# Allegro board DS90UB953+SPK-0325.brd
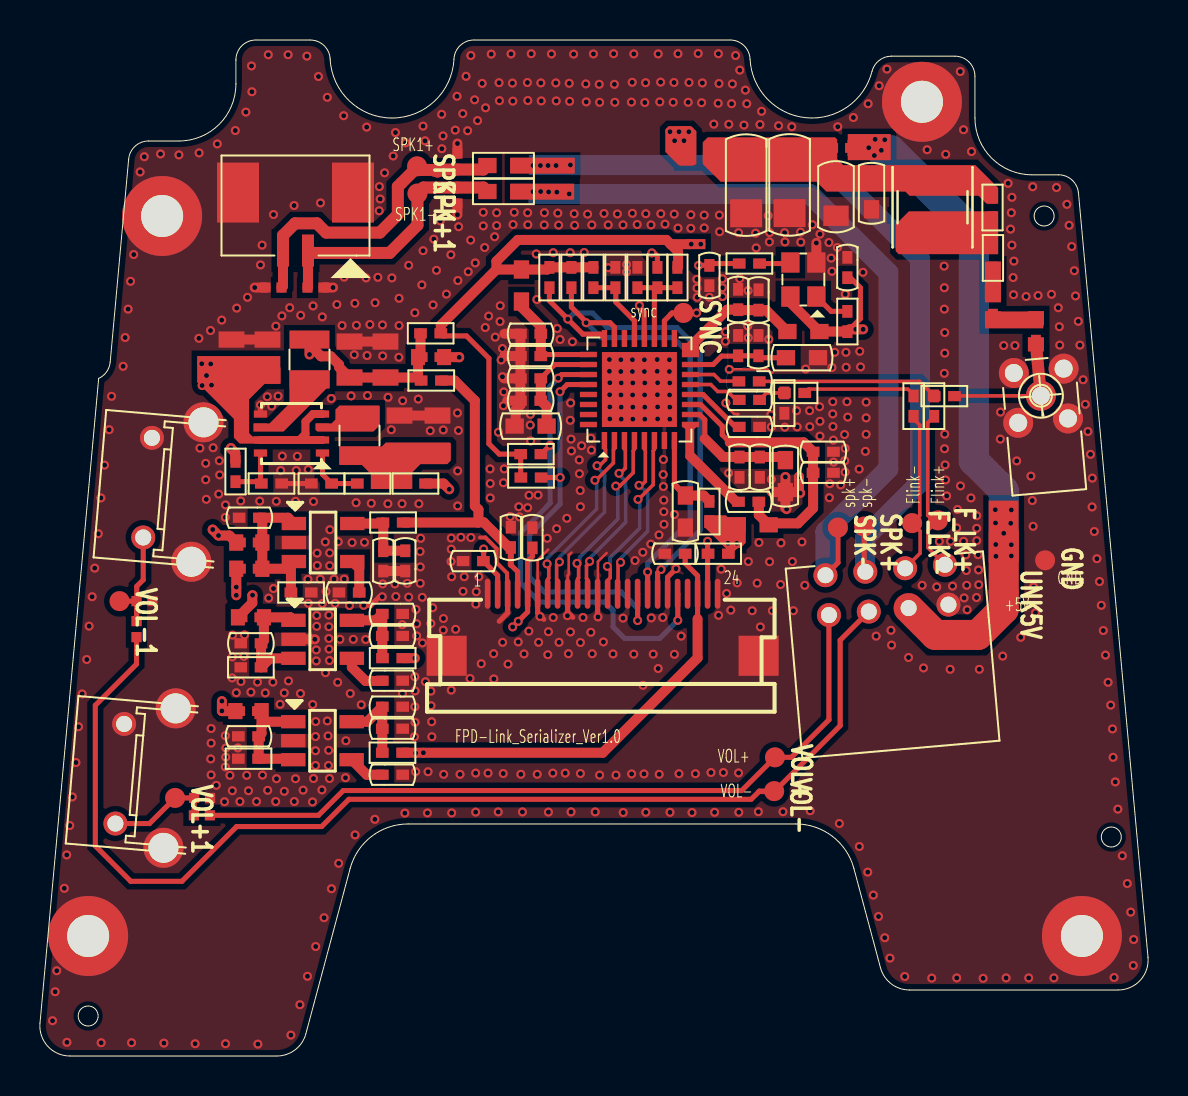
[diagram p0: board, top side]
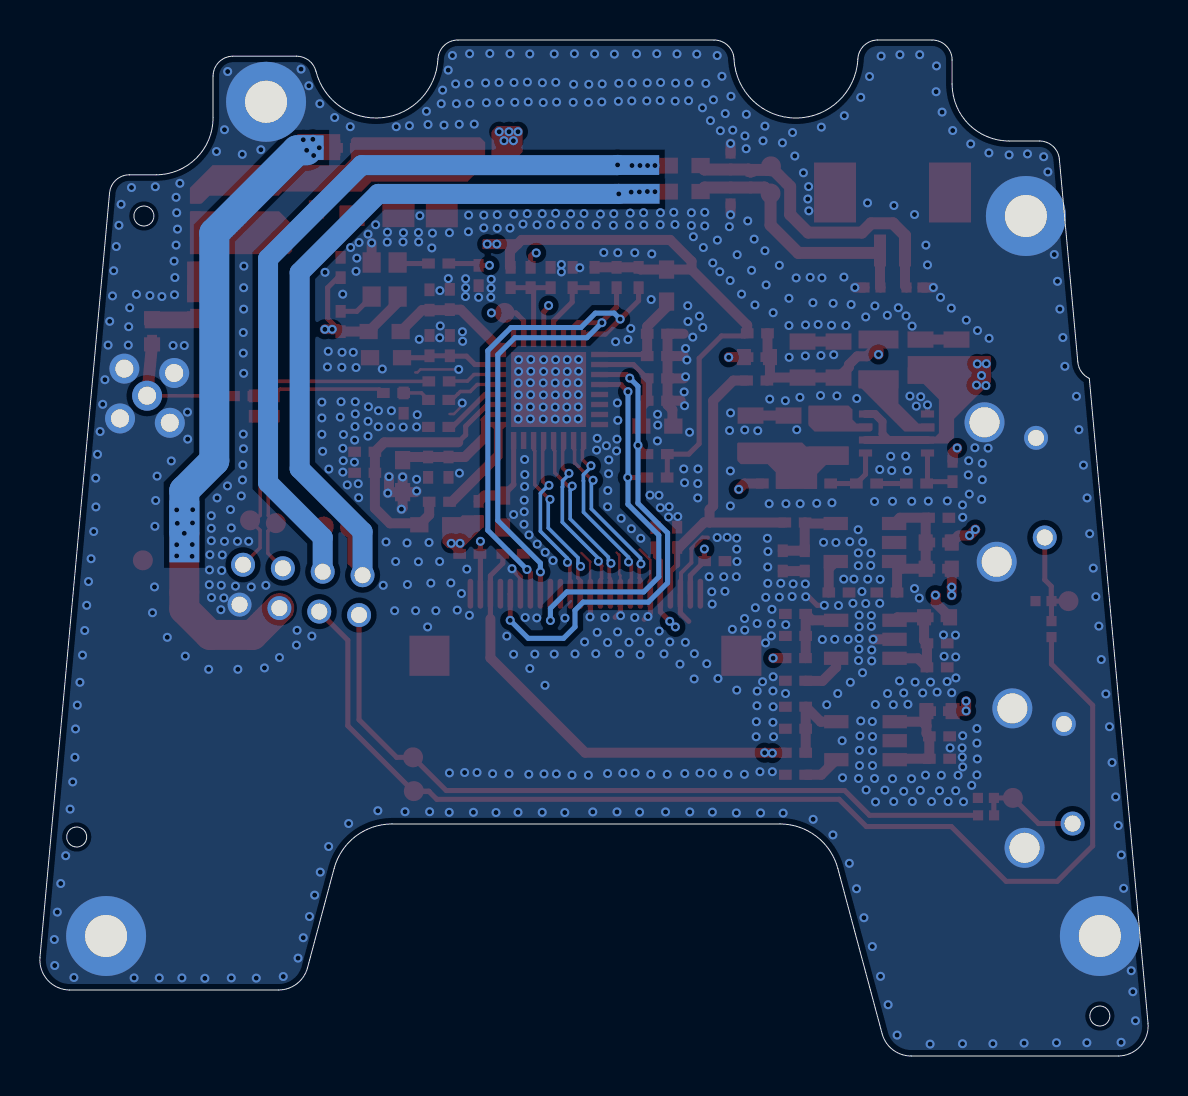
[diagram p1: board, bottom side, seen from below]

Outline 55.41 x 50.8 mm; copper layers: TOP, GND, POWER, BOTTOM. Coordinates in mm from the lower left corner of the outline.
Outline path: circle c2.41,2 r0.5 ; circle c50.22,42 r0.5 ; circle c53.58,10.95 r0.5 ; 1.49,0 arc(0.39,0.49) 0,1.64 2.93,33.88 arc(3.33,34.21) 3.51,34.7 4.43,44.84 arc(4.76,45.49) 5.43,45.75 6.95,45.75 arc(8.96,46.58) 9.8,48.6 9.8,49.8 arc(10.09,50.51) 10.8,50.8 13.51,50.8 arc(14.2,50.52) 14.51,49.85 arc(17.61,46.9) 20.7,49.85 arc(21.01,50.52) 21.7,50.8 34.51,50.8 arc(35.2,50.52) 35.51,49.85 arc(38.3,46.92) 41.61,49.24 arc(41.97,49.78) 42.58,49.99 45.76,49.99 arc(46.47,49.7) 46.76,48.99 46.76,46.91 arc(47.59,44.89) 49.61,44.06 50.94,44.06 arc(51.61,43.8) 51.94,43.15 55.41,4.94 arc(55.03,3.79) 53.92,3.3 43.48,3.3 arc(42.57,3.61) 42.03,4.41 40.7,9.38 arc(39.63,10.98) 37.81,11.6 18.41,11.6 arc(16.58,10.98) 15.51,9.38 13.3,1.11 arc(12.76,0.31) 11.85,0 1.49,0

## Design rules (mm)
net group N133411: nets N133411 N133415

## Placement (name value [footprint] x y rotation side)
C1  10uF  [C0603]  24.54 31.49 180 top
C2  0.1uF  [C0402]  24.54 32.76 180 top
C3  0.01uF  [C0402]  24.54 33.88 180 top
C4  10uF  [C0603]  38.11 34.91 0 top
C5  0.1uF  [C0402]  35.93 35.52 90 top
C6  0.01uF  [C0402]  34.92 35.52 90 top
C7  10uF  [C0603]  37.28 28.99 270 top
C8  0.1uF  [C0402]  36 29.44 270 top
C9  0.01uF  [C0402]  34.99 29.44 270 top
C10  0.033uF  [C0402]  35.46 33.73 0 top
C12  1uF  [C0402]  24.54 35 180 top
C13  0.01uF  [C0402]  24.54 36.11 180 top
C14  1uF  [C0402]  34.92 37.82 90 top
C15  0.01uF  [C0402]  35.93 37.8 90 top
C16  1uF  [C0402]  39.17 30.21 0 top
C17  0.01uF  [C0402]  39.17 29.16 0 top
C18  0.022uF  [C0402]  35.44 27.71 180 top
C19  0.1uF  [C0402]  35.48 31.45 0 top
C20  10uF  [C0603]  32.28 27.22 270 top
C21  NP  [C0402]  21.67 24.74 0 top
C22  @4.7uF/25V  [C0805]  39.81 42.96 270 top
C23  @0.1uF/25V  [C0603]  41.59 43.13 270 top
C36  0.01uF  [C0402]  40.38 39.42 90 top
C6893  1UF  [C0402]  10.43 15.98 0 top
C6894  1UF  [C0402]  17.63 16.36 180 top
C6895  100nF  [C0402]  17.63 14.06 180 top
C6999  2.2UF  [C0402]  17.63 17.46 0 top
C7011  1UF  [C0402]  10.47 26.91 0 top
C7012  1UF  [C0402]  17.17 24.75 90 top
C7013  100nF  [C0402]  15.46 23.17 0 top
C7014  2.2UF  [C0402]  18.27 24.75 270 top
C7019  NC  [C1206]  37.49 43.55 270 top
C7020  NC  [C1206]  35.32 43.54 270 top
C7321  @100PF  [2P0402R]  20.88 44.72 270 top
C7322  @100PF  [2P0402R]  20.88 43.02 90 top
C7346  22UF/10V  [2P0805R]  9.58 34.92 270 top
C7347  22UF/10V  [2P0805R]  11.38 34.92 270 top
C7348  22UF  [2P0805R]  19.88 31.12 270 top
C7349  22UF  [2P0805R]  17.98 31.12 270 top
C7350  22UF  [2P0805R]  15.48 34.82 270 top
C7351  22UF  [2P0805R]  17.28 34.82 270 top
C7352  0.033uF  [C0402]  35.48 32.8 0 top
C7501  @100nF/25V_2  [2P0402R]  19.88 43.82 90 top
C7502  NC  [C0402]  33.48 39.02 90 top
C7503  1UF  [C0402]  10.55 20.63 0 top
C7504  1UF  [C0402]  17.63 21 180 top
C7505  100nF  [C0402]  17.63 18.76 180 top
C7506  2.2UF  [C0402]  17.63 22.1 0 top
C7508  0.1uF  [C0402]  23.55 25.93 90 top
C7509  0.1uF  [C0402]  24.63 25.91 90 top
C7510  0.1uF  [C0402]  31.76 25.11 180 top
F_LK+  DNI(TP1_3)  [TP32]  44.91 26.78 0 top
F_LK-  DNI(TP1_3)  [TP32]  43.62 26.64 0 top
GND  DNI(TP1_3)  [TP32]  50.27 24.78 0 top
H1  HOLE1  [HOLE4P0CIR2P1]  2.41 6 0 top
H2  HOLE1  [HOLE4P0CIR2P1]  52.11 6 0 top
H3  HOLE1  [HOLE4P0CIR2P1]  44.11 47.71 0 top
H4  HOLE1  [HOLE4P0CIR2P1]  6.11 42 0 top
J1  CON26  [FPC0520D-M24-00RW]  21.39 23.11 180 top
J2  @JC3.660.047  [MMCXKWE]  50.06 33.01 275 top
J3  -  [FWF20006-D08B22W5B]  42.36 23.3 275 top
J2527  -  [Y2-8090V]  4.21 16.6 265 top
J2528  -  [Y2-8090V]  5.6 30.91 265 top
J2529  A1500WV-S-02P  [4PIN-CON-WF12502-01200]  12.78 42.32 180 top
L1  @MPZ1005F470ETD  [2P0402R_0603]  49.81 36.23 90 top
L2  @MPZ1005S331ETD  [2P0402R_0603]  47.66 37.53 90 top
L3  @10uH LQH3NPN100NG0  [SL2520_30X30_40X40]  44.64 42.43 270 top
L4  BLM18AG102SN1  [L0603H0_95]  24.08 38.52 90 top
L5  BLM18AG102SN1  [L0603H0_95]  38.18 36.22 0 top
L6  BLM18AG102SN1  [L0603H0_95]  35.64 26.56 180 top
L1003  1.5UH/0.65A  [2520_2016]  15.98 31.02 270 top
L1004  1.5UH/0.65A  [2520_2016]  13.48 34.82 90 top
R1  0R  [R0402]  30.88 38.92 90 top
R2  2K  [R0402]  26.58 38.92 270 top
R3  2K  [R0402]  25.48 38.92 270 top
R4  @49.9R/NC  [R0402]  37.23 32.64 270 top
R5  10K  [R0402]  27.68 38.92 270 top
R6  402R 1%  [R0402]  28.78 38.92 270 top
R7  10K  [R0402]  33.48 27.22 90 top
R8  @0R  [R0402]  47.66 39.9 90 top
R9  @4.02K_1%  [R0402]  47.64 42.42 90 top
R19  10K  [R0402]  40.38 36.72 90 top
R20  NC  [R0402]  35.48 39.62 180 top
R2567  806K/5%  [R0402]  16.38 28.62 0 top
R2568  825K/5%  [R0402]  14.08 28.62 0 top
R7209  1K  [2P0402R]  8.1 12.03 180 top
R7281  100K/5%  [R0402]  10.43 14.86 180 top
R7282  100K/5%  [R0402]  13.06 23.17 0 top
R7286  NC  [2P0402R_0603]  32.98 44.93 180 top
R7288  1K  [2P0402R]  4.83 21.34 90 top
R7291  0R  [R0603]  23.18 44.52 180 top
R7292  0R  [R0603]  23.18 43.22 180 top
R7293  0R  [2P0402R_0603]  40.09 45.4 180 top
R7297  806K/5%  [R0402]  9.78 29.22 90 top
R7298  412K/5%  [R0402]  11.58 28.62 180 top
R7302  NC  [R0402]  45.23 32.99 180 top
R7303  0R  [R0402]  17.63 15.16 0 top
R7304  0R  [R0402]  17.66 26.67 0 top
R7305  0R  [R0402]  18.78 28.62 0 top
R7306  0R  [R0402]  19.54 36.13 180 top
R7307  0R  [R0402]  37.74 33.15 0 top
R7308  NC  [R0402]  31.88 38.92 90 top
R7309  40.2K  [R0402]  29.88 38.92 270 top
R7310  NC  [R0402]  19.57 33.77 180 top
R7311  0R  [2P0402R_0603]  10.43 17.24 180 top
R7312  0R  [2P0402R_0603]  10.47 25.67 180 top
R7313  NC  [2P0402R_0603]  10.47 24.36 180 top
R7314  100K/5%  [R0402]  10.55 19.43 180 top
R7316  NC  [2P0402R_0603]  10.55 21.93 180 top
R7317  NC  [R0402]  17.64 19.89 0 top
R7318  NC  [2P0402R_0603]  19.56 34.94 0 top
R7319  @0R  [R0402]  44.72 32.49 90 top
R7320  @0R  [R0402]  43.69 32.49 90 top
R7321  10K  [R0402]  24.56 28.92 0 top
R7322  10K  [R0402]  24.55 30.09 0 top
R7323  10K  [R0402]  33.92 25.11 180 top
SPK+  DNI(TP1_3)  [TP32]  41.22 26.47 0 top
SPK+1  DNI(TP1_3)  [TP32]  18.88 43.12 0 top
SPK-  DNI(TP1_3)  [TP32]  39.91 26.42 0 top
SPK-1  DNI(TP1_3)  [TP32]  18.86 44.48 0 top
SYNC  DNI(TP1_3)  [TP32]  32.18 37.15 0 top
T31  LESD9D5.0CT5G  [2P0402R]  8.11 12.9 0 top
T32  LESD9D5.0CT5G  [2P0402R]  5.23 22.74 0 top
T33  LESD9D5.0CT5G  [2P0402R]  11.68 38.42 180 top
T34  LESD9D5.0CT5G  [2P0402R]  13.78 38.42 0 top
U1  DS90UB953TRHBTQ1  [QFN32-0_5-SQ5H0_85]  29.98 33.32 90 top
U2105  SGM2019-3.3YN5G/TR  [SOT23-5H1_0]  14.13 15.76 270 top
U2106  SGM2019-1.8YN5G/TR  [SOT23-5H1_0]  14.16 25.67 270 top
U2109  MP2122GJ  [TSOP8-0_65-SQ3_0H1_0]  12.58 31.12 90 top
U2110  SGM2019-1.2YN5G/TR  [SOT23-5H1_0]  14.14 20.83 270 top
UNK5V  DNI(TP1_3)  [TP32]  48.23 23.65 0 top
VOL+  DNI(TP1_3)  [TP32]  36.76 14.93 0 top
VOL+1  DNI(TP1_3)  [TP32]  6.76 12.9 0 top
VOL-  DNI(TP1_3)  [TP32]  36.72 13.24 0 top
VOL-1  DNI(TP1_3)  [TP32]  3.98 22.74 0 top
Y1  ASDMB-50.000MHZ  [CRY4-2520]  38.18 38.82 90 top

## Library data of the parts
C1-C10 C12-C23 C36 C7019 C7020 C7352 C7502 C7508-C7510 = CAP NP
C6893 C6894 C7011 C7012 C7503 C7504 = CAP NP_1
C6895 C7013 C7505 = CAP NP_0
C6999 C7014 C7506 = 0402C-47p_1
C7321 C7322 C7501 = CAP NP: Tolerance: #TOL; User Part Number: HAMP; signal model: DEFAULT_CAPACITOR_0.001pF_1_2
C7346-C7351 = CAP NP: Tolerance: #TOL; User Part Number: HAMP
F_LK+ F_LK- GND SPK+ SPK+1 SPK- SPK-1 SYNC UNK5V VOL+ VOL+1 VOL- VOL-1 = TP
H1-H4 = HEADER 1_0
J1 = CON26: User Part Number: HAMP; Tolerance: #TOL
J2 = BNC_0
J3 = CONN_6_M4_SIMCARD_7
J2527 J2528 = TS-022_1
J2529 = TS-022_0
L1 L2 = INDUCTOR_0: User Part Number: HAMP; Tolerance: #TOL
L3 = INDUCTOR IRON: User Part Number: HAMP; Tolerance: #TOL
L4-L6 = INDUCTOR_0
L1003 L1004 = INDUCTOR
R1-R9 R19 R20 R7291 R7292 R7302-R7310 R7317 R7319-R7323 = R
R2567 R2568 R7281 R7282 R7297 R7298 R7314 = R_6
R7209 R7288 = R_6: Tolerance: #TOL; User Part Number: HAMP
R7286 R7293 R7311-R7313 R7316 R7318 = R: User Part Number: HAMP; Tolerance: #TOL
T31-T34 = GCDIODE_ESD: Tolerance: #TOL; User Part Number: HAMP
U1 = ds90ub953-q1
U2105 U2106 U2110 = TPS22902_1
U2109 = SW_SPST_1
Y1 = ASDMB-50.000MHZ

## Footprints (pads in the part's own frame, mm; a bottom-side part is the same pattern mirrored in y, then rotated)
2P0402R
  rect 0.508x0.508 smd: 1(-0.4,0) 2(0.4,0)
2P0402R_0603
  rect 0.7x0.8 smd: 1(-0.65,0) 2(0.65,0)
2P0805R
  rect 0.813x1.295 smd: 1(-0.9,0) 2(0.9,0)
4PIN-CON-WF12502-01200
  rect 0.6x1.6 smd: 1(-0.625,2.05) 2(0.625,2.05)
  rect 2.1x3 smd: 3(-2.875,-0.85) 4(2.875,-0.85)
2520_2016
  rect 0.9x2 smd: 1(-1,0) 2(1,0)
C0402
  rect 0.635x0.508 smd: 1(-0.508,0) 2(0.508,0)
C0603
  rect 0.914x0.762 smd: 1(-0.8,0) 2(0.8,0)
C0805
  rect 1.016x1.27 smd: 1(-0.953,0) 2(0.953,0)
C1206
  rect 1.397x1.6 smd: 1(-1.41,0) 2(1.41,0)
CRY4-2520
  rect 1.016x0.914 smd: 1(-0.851,-0.65) 2(0.851,-0.65) 3(0.851,0.65) 4(-0.851,0.65)
FPC0520D-M24-00RW
  oval 0.279x1.499 smd: 1(-1,0) 2(-1.5,0) 3(-2,0) 4(-2.5,0) 5(-3,0) 6(-3.5,0) 7(-4,0) 8(-4.5,0) 9(-5,0) 10(-5.5,0) 11(-6,0) 12(-6.5,0) 13(-7,0) 14(-7.5,0) 15(-8,0) 16(-8.5,0) 17(-9,0) 18(-9.5,0) 19(-10,0) 20(-10.5,0) 21(-11,0) 22(-11.5,0) 23(-12,0) 24(-12.5,0)
  rect 2.007x2.007 smd: 25(1.05,3.1) 26(-14.55,3.1)
FWF20006-D08B22W5B
  round 1.2 hole 0.8: 1(-1,3) 2(-1,1) 3(-1,-1) 4(-1,-3) 5(1,-3) 6(1,-1) 7(1,1) 8(1,3)
HOLE4P0CIR2P1
  round 4 hole 2.1: 1(0,0)
L0603H0_95
  rect 0.914x0.762 smd: 1(-0.8,0) 2(0.8,0)
MMCXKWE
  round 1.5 hole 0.9: 1(0,0) 2(1.25,1.25) 3(1.25,-1.25) 4(-1.25,-1.25) 5(-1.25,1.25)
QFN32-0_5-SQ5H0_85
  rect 0.851x0.269 smd: 1(-2.55,1.75) 2(-2.55,1.25) 3(-2.55,0.749) 4(-2.55,0.249) 5(-2.55,-0.249) 6(-2.55,-0.749) 7(-2.55,-1.25) 8(-2.55,-1.75) 17(2.55,-1.75) 18(2.55,-1.25) 19(2.55,-0.749) 20(2.55,-0.249) 21(2.55,0.249) 22(2.55,0.749) 23(2.55,1.25) 24(2.55,1.75)
  rect 0.269x0.851 smd: 9(-1.75,-2.55) 10(-1.25,-2.55) 11(-0.749,-2.55) 12(-0.249,-2.55) 13(0.249,-2.55) 14(0.749,-2.55) 15(1.25,-2.55) 16(1.75,-2.55) 25(1.75,2.55) 26(1.25,2.55) 27(0.749,2.55) 28(0.249,2.55) 29(-0.249,2.55) 30(-0.749,2.55) 31(-1.25,2.55) 32(-1.75,2.55)
  rect 3.749x3.749 smd: 33(0,0)
R0402
  rect 0.635x0.508 smd: 1(-0.508,0) 2(0.508,0)
R0603
  rect 0.914x0.762 smd: 1(-0.8,0) 2(0.8,0)
SL2520_30X30_40X40
  rect 1.092x3.683 smd: 1(-1.501,0) 2(1.501,0)
SOT23-5H1_0
  rect 0.66x1.219 smd: 1(-0.95,-1.46) 2(0,-1.46) 3(0.95,-1.46) 4(0.95,1.46) 5(-0.95,1.46)
TP32
  round 1 smd: 1(0,0)
TSOP8-0_65-SQ3_0H1_0
  rect 0.356x0.66 smd: 1(-0.975,-1.55) 2(-0.325,-1.55) 3(0.325,-1.55) 4(0.975,-1.55) 5(0.975,1.55) 6(0.325,1.55) 7(-0.325,1.55) 8(-0.975,1.55)
Y2-8090V
  round 1.2 hole 0.8: 1(5,0) 2(0,0)
  round 2 hole 1.5: 3(6,2.5) 4(-1,2.5)

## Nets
GND: C1.2 C2.2 C3.2 C4.2 C5.2 C6.2 C7.2 C8.2 C9.2 C12.2 C13.2 C14.2 C15.2 C16.2 C17.2 C19.2 C20.2 C21.1 C22.2 C23.2 C36.2 C6893.1 C6894.1 C6895.1 C6999.2 C7011.1 C7012.1 C7013.1 C7014.2 C7019.2 C7020.2 C7321.1 C7322.1 C7346.1 C7347.1 C7348.1 C7349.1 C7350.1 C7351.1 C7502.1 C7503.1 C7504.1 C7505.1 C7506.2 C7508.2 C7509.2 C7510.2 GND.1(TP) H1.1 H2.1 H3.1 H4.1 J1.1 J1.3 J1.6 J1.9 J1.12 J1.15 J1.19 J1.24 J1.25 J1.26 J2.2 J2.3 J2.4 J2.5 J3.8(GND2) J2527.2(S2) J2527.3(GND1) J2527.4(GND2) J2528.2(S2) J2528.3(GND1) J2528.4(GND2) J2529.3(GND1) J2529.4(GND2) R4.2 R6.1 R2568.1 R7281.2 R7282.2 R7298.1 R7309.1 R7314.2 T31.2 T32.2 T33.2 T34.2 U1.7(RES0) U1.33(DAP) U2105.2(GND) U2106.2(GND) U2109.5(GND) U2110.2(GND) Y1.2(GND)
VDD_1V8: C36.1 L4.2 L5.2 L6.2 R2.1 R3.1 R5.1 R7.1 R19.1 R7306.1 R7308.2 R7321.1 R7322.1 R7323.1 Y1.4(VDD)
VDD_5V: C7346.2 C7347.2 R7286.2 R7311.2 R7312.2 U2109.2(EN2) U2109.4(EN1) U2109.7(IN)
VDD_LDO: R7316.2 R7318.2
CAM_1V2: C7509.1 J1.5 R7305.2 R7317.2
CAM_1V8: C7508.1 J1.4 R7304.2 R7310.1
CAM_3V3: C7510.1 J1.22 R7303.2 R7313.2
CAM_CLK: C21.2 J1.2 R1.2
CAM_CLKO: R1.1 R7308.1 R7309.2 U1.19(CLK_OUT/IDX)
CAM_PWD: J1.16 R7321.2 U1.28(GPIO3)
CAM_RST: J1.20 R7322.2 U1.27(GPIO2)
CAM_SCL: J1.18 R3.2 U1.24(I2C_SCL)
CAM_SDA: J1.17 R2.2 U1.23(I2C_SDA)
CAM_SYNC: J1.23 R7323.2 SYNC.1(TP) U1.18(GPIO1)
CLK_IN: C7502.2 R20.2 U1.20(CLKIN)
CSI_CKN: J1.13 U1.6(CSI_CLKN)
CSI_CKP: J1.14 U1.5(CSI_CLKP)
CSI_D0N: J1.10 U1.4(CSI_D0N)
CSI_D0P: J1.11 U1.3(CSI_D0P)
CSI_D1N: J1.7 U1.2(CSI_D1N)
CSI_D1P: J1.8 U1.1(CSI_D1P)
FDP-LINK+: C10.2 R7302.2 R7319.2
FDP-LINK-: R7307.2 R7320.2
POC_V: C22.1 C23.1 C7019.1 C7020.1 L3.1 R9.2 R7286.1 R7293.2
PWR_5V: J3.7(PWR_5V) R7293.1 UNK5V.1
SPK+: J3.4(SPK-) R7292.1 SPK-.1(TP)
SPK-: J3.3(SPK+) R7291.1 SPK+.1(TP)
VOL+: J3.5(VOLUME+) R7209.1 VOL+.1(TP)
VOL-: J3.6(VOLUME-) R7288.1 VOL-.1(TP)
N00294: C1.1 C2.1 C3.1 U1.26(VDDD_CAP)
N00623: C4.1 C5.1 C6.1 U1.15(VDDDRV_CAP)
N01072: C7.1 C8.1 C9.1 U1.10(VDDPLL_CAP)
N03572: C10.1 U1.14(DOUT+)
N03592: C7352.1 U1.13(DOUT-)
N03606: J2.1 L1.1 R7302.1
N03646: C7352.2 R4.1 R7307.1
N04688: C12.1 C13.1 L4.1 U1.25(VDDD)
N05216: C14.1 C15.1 L5.1 U1.16(VDDDRV)
N05348: C16.1 C17.1 C18.1 L6.1 U1.11(VDDDPLL)
N05546: C18.2 U1.9(LPF1)
N05630: C19.1 U1.12(LPF2)
N08569: R5.2 R6.2 U1.21(MODE)
N08620: C20.1 R7.2 U1.8(PDB)
N10872: L1.2 L2.1
N10876: L2.2 R8.1
N10907: L3.2 R8.2 R9.1
N20067: R19.2 Y1.1(STB)
N20534: R20.1 Y1.3(OUT)
N40133: C6893.2 R7281.1 R7311.1 U2105.1(VIN) U2105.3(EN)
N40219: C6895.2 U2105.4(BP/FB)
N40223: C6894.2 C6999.1 R7303.1 U2105.5(VOUT)
N40778: C7011.2 R7282.1 R7312.1 R7313.1 U2106.1(VIN) U2106.3(EN)
N40864: C7013.2 U2106.4(BP/FB)
N40868: C7012.2 C7014.1 R7304.1 U2106.5(VOUT)
N92182: J2527.1(S1) R7209.2 T31.1 VOL+1.1(TP)
N92991: J2528.1(S1) R7288.2 T32.1 VOL-1.1(TP)
N121438: L1003.1 U2109.3(SW2)
N121471: R2567.1 R2568.2 U2109.1(FB2)
N121478: C7348.2 C7349.2 L1003.2 R2567.2 R7305.1
N129833: R7297.1 R7298.2 U2109.8(FB1)
N129837: C7350.2 C7351.2 L1004.2 R7297.2 R7306.2 R7310.2 R7318.1
N131151: L1004.1 U2109.6(SW1)
N133411: C7322.2 C7501.1 J2529.1 R7292.2 SPK+1.1(TP) T34.1
N133415: C7321.2 C7501.2 J2529.2 R7291.2 SPK-1.1(TP) T33.1
N134026: F_LK+.1(TP) J3.1(FDP-LINK+) R7319.1
N134032: F_LK-.1(TP) J3.2(FDP-LINK-) R7320.1
N180611: C7503.2 R7314.1 R7316.1 U2110.1(VIN) U2110.3(EN)
N180695: C7504.2 C7506.1 R7317.1 U2110.5(VOUT)
N180699: C7505.2 U2110.4(BP/FB)

Pads without a net: J1 21; U1 17 22 29 30 31 32

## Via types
v1: diameter 0.45, hole 0.249, TOP to BOTTOM, 879 vias

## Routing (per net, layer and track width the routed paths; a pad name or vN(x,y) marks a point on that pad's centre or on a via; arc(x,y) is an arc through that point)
GND: length 47.3
  TOP w0.127: 36.64,34.18 36.53,34.18 36.38,34.33 v1(34.47,34.33) ; 25.42,25.32 24.89,24.79 J1.6 ; J1.12 27.9,23.13 27.9,24.72 28.34,25.15 ; 26.58,25.17 26.44,25.04 26.44,24.08 26.39,24.02 J1.9 ; v1(34.3,32.65) 34.33,32.62 34.33,32.48 34.71,32.1 34.93,32.1
  TOP w0.2: J1.3 23.36,23.14 23.36,24.15 22.84,24.67 22.84,25.36 22.28,25.92 22.01,25.92
  TOP w0.254: v1(17.12,22.96) 16.98,22.96 16.55,22.53 v1(16.19,22.53) ; 23.32,32.81 23.37,32.76 ; v1(31.81,24.36) 31.39,23.94 J1.19 ; J1.12 27.89,21.97 v1(27.91,21.95) ; v1(23.13,33.96) 23.21,33.88 ; 26.65,21.93 26.39,22.19 J1.9 ; R7298.1 R2568.1 ; U2109.5 v1(11.03,32.55) ; J1.6 24.89,22.14 25.2,21.83 ; 23.22,34.99 23.22,35 ; J1.3 23.39,22.15 22.97,21.73 ; 23.22,36.1 23.23,36.11
  TOP w0.327: v1(37.28,28.95) 37.28,28.98 ; 37.99,28.19 37.97,28.19
  TOP w0.5: C1.2 23.79,31.54 23.79,32.31 24.03,32.56 C2.2 ; 23.21,33.88 C3.2 ; C3.2 C12.2 ; C3.2 C2.2 ; C7321.1 v1(20.88,45.62) ; 23.37,32.76 C2.2 ; U2110.2 v1(13.75,20.83) ; C7349.1 C7348.1 ; C7.2 v1(37.28,28.95) ; C7.2 36.63,28.19 v1(36.58,28.24) ; C7.2 37.28,27.4 v1(37.34,27.34) ; C7.2 37.97,28.19 ; C12.2 23.22,35 ; C12.2 C13.2 23.23,36.11 ; 37.97,28.19 v1(38.02,28.14) ; 37.97,28.19 37.96,28.2 v1(37.96,28.96) ; C7014.2 C7012.1 ; C7350.1 C7351.1 ; C7322.1 v1(20.88,42.06) ; Y1.2 v1(38.83,40.65) ; T34.2 v1(14.66,38.42) ; C7347.1 C7346.1 ; T33.2 v1(10.74,38.42)
  GND w0.127: 28.33,28.83 28.21,28.43
  POWER w0.127: 9.19,23.46 9.39,23.66 9.39,23.73 9.45,23.8 9.72,24
  vias: v1(0.63,1.76) v1(0.84,4.26) v1(0.76,3.21) v1(1.22,8.38) v1(1.34,10.05) v1(1.35,0.68) v1(1.49,11.52) v1(1.62,12.95) v1(1.8,14.67) v1(1.93,16.46) v1(2.11,18.1) v1(2.34,19.82) v1(2.46,21.49) v1(2.61,22.96) v1(2.74,24.39) v1(2.92,26.11) v1(3.05,27.9) v1(3.06,0.66) v1(3.23,29.54) v1(3.46,31.31) v1(3.58,32.98) v1(4.16,34.48) v1(4.26,35.92) v1(4.41,37.34) v1(4.53,38.73) v1(4.58,0.66) v1(4.69,40.07) v1(5.01,44.2) v1(5.22,44.96) v1(6.03,45.1) v1(6.2,0.64) v1(6.95,45.05) v1(7.76,0.61) v1(7.96,45.15) v1(7.95,35.88) v1(8,30.39) v1(8.29,29.63) v1(8.29,28.81) v1(8.32,27.83) v1(8.53,36.27) v1(8.54,14.85) v1(8.56,16.37) v1(8.56,15.64) v1(8.56,14.05) v1(8.66,30.41) v1(8.82,13.53) v1(8.87,45.6) v1(8.94,28.09) v1(8.97,29.76) v1(8.99,29.05) v1(9.09,36.79) v1(9.23,12.71) v1(9.28,27.55) v1(9.27,26.93) v1(9.27,16.01) v1(9.3,15.4) v1(9.29,14.94) v1(9.27,14.45) v1(9.28,0.61) v1(9.5,14.03) v1(9.63,21.04) v1(9.62,19.95) v1(9.61,18.9) v1(9.62,13.26) v1(9.77,46.27) v1(9.84,37.39) v1(9.82,18.16) v1(9.9,15.4) v1(10.04,27.75) v1(10,12.72) v1(10.05,18.72) v1(10.23,21.05) v1(10.2,19.98) v1(10.3,47.19) v1(10.34,14.03) v1(10.38,37.93) v1(10.43,13.26) v1(10.58,49.5) v1(10.6,48.21) v1(10.55,18.19) v1(10.83,12.72) v1(10.88,18.69) v1(10.9,0.59) v1(11.03,39.55) v1(10.99,27.74) v1(11.11,40.54) v1(11.13,14.04) v1(11.27,18.15) v1(11.42,50.06) v1(11.37,32.96) v1(11.44,22.89) v1(11.39,13.28) v1(11.59,32.49) v1(11.68,42.07) v1(11.68,23.37) v1(11.65,18.69) v1(11.8,36.49) v1(11.82,27.73) v1(11.83,13.86) v1(11.79,12.72) v1(11.91,32.99) v1(12.04,29.27) v1(12.01,17.58) v1(12.1,37) v1(12.12,29.99) v1(12.22,18.15) v1(12.22,13.23) v1(12.41,50.06) v1(12.43,18.75) v1(12.49,37.41) v1(12.55,1.04) v1(12.71,42.52) v1(12.74,17.56) v1(12.72,12.72) v1(12.82,29.27) v1(12.78,27.73) v1(12.78,13.86) v1(12.87,29.98) v1(13.04,37.03) v1(13.03,18.12) v1(13,2.56) v1(13.16,13.29) v1(13.35,49.99) v1(13.42,29.32) v1(13.4,23.83) v1(13.42,22.63) v1(13.38,3.98) v1(13.64,17.57) v1(13.63,12.7) v1(13.66,37.5) v1(13.68,27.72) v1(13.68,13.87) v1(13.84,22.02) v1(13.84,21.48) v1(13.82,20.3) v1(13.82,19.75) v1(13.79,16.72) v1(13.78,15.97) v1(13.78,15.26) v1(13.78,14.52) v1(13.79,5.47) v1(13.93,48.97) v1(13.86,25.14) v1(13.87,24.52) v1(14.03,42.65) v1(14.02,23.84) v1(14.12,36.95) v1(14.12,22.62) v1(14.1,13.3) v1(14.21,6.91) v1(14.27,25.7) v1(14.31,23.22) v1(14.28,19.16) v1(14.37,47.93) v1(14.37,16.75) v1(14.41,16) v1(14.44,15.28) v1(14.43,14.52) v1(14.5,26.31) v1(14.49,25.15) v1(14.49,24.51) v1(14.45,22.04) v1(14.45,21.46) v1(14.45,20.87) v1(14.46,20.34) v1(14.48,19.77) v1(14.48,13.87) v1(14.57,32.87) v1(14.58,8.36) v1(14.71,23.84) v1(14.76,22.63) v1(14.85,37.57) v1(14.92,25.71) v1(14.89,18.68) v1(14.94,9.63) v1(15,20.83) v1(15.11,36.52) v1(15.19,47.01) v1(15.21,38.94) v1(15.22,23.84) v1(15.3,15.76) v1(15.28,13.91) v1(15.48,22.52) v1(15.52,18.12) v1(15.56,33) v1(15.61,25.67) v1(15.72,35.06) v1(15.67,20.83) v1(15.75,37.63) v1(15.83,36.53) v1(15.81,27.66) v1(15.76,11.05) v1(16.07,17.56) v1(16.23,25.68) v1(16.34,46.44) v1(16.31,38.9) v1(16.29,20.82) v1(16.36,35.02) v1(16.38,33.02) v1(16.5,36.57) v1(16.57,27.63) v1(16.76,37.66) v1(16.75,11.83) v1(16.9,38.93) v1(16.97,43.47) v1(17.01,42.85) v1(16.96,42.26) v1(17.13,36.55) v1(17.14,35) v1(17.14,23.6) v1(17.23,44.16) v1(17.41,32.93) v1(17.4,27.61) v1(17.6,38.9) v1(17.57,31.31) v1(17.66,45) v1(17.78,46.17) v1(17.75,23.6) v1(17.8,22.97) v1(17.96,37.88) v1(17.96,36.52) v1(17.95,34.93) v1(18.14,32.76) v1(18.11,27.61) v1(18.12,21.56) v1(18.13,18.12) v1(18.28,45.66) v1(18.25,12.14) v1(18.44,39.53) v1(18.37,23.63) v1(18.44,22.94) v1(18.73,15.96) v1(18.75,37.16) v1(18.81,22.33) v1(18.84,21.61) v1(18.84,21) v1(18.75,18.96) v1(18.76,18.25) v1(18.75,17.46) v1(18.76,16.68) v1(18.79,14.21) v1(18.92,32.84) v1(18.95,27.61) v1(19.04,25.88) v1(19.01,25.22) v1(19.02,24.45) v1(19.02,23.63) v1(19.1,38.55) v1(19.12,22.93) v1(19.13,20.65) v1(19.16,46.49) v1(19.16,40.26) v1(19.25,45.76) v1(19.28,18.71) v1(19.41,14.21) v1(19.38,12.15) v1(19.52,31.26) v1(19.64,22.41) v1(19.55,21.62) v1(19.55,18.24) v1(19.56,17.51) v1(19.59,16.71) v1(19.6,15.96) v1(19.7,40.84) v1(19.66,37.55) v1(19.83,39.28) v1(20.02,41.75) v1(20.09,47.08) v1(20.1,45.36) v1(20.16,46) v1(20.17,31.3) v1(20.18,21.87) v1(20.17,21.29) v1(20.19,14.08) v1(20.33,38.09) v1(20.55,40.06) v1(20.57,25.89) v1(20.57,25.34) v1(20.56,24.72) v1(20.59,23.96) v1(20.57,18.29) v1(20.59,12.15) v1(20.77,46.29) v1(20.79,21.33) v1(20.86,47.98) v1(20.94,41.46) v1(20.9,38.77) v1(20.88,32.15) v1(20.93,31.27) v1(20.89,29.25) v1(20.89,27.5) v1(21.01,14.08) v1(21.14,47.12) v1(21.05,25.93) v1(21.22,23.96) v1(21.16,23.23) v1(21.31,48.98) v1(21.39,46.26) v1(21.42,39.21) v1(21.54,40.79) v1(21.51,18.87) v1(21.55,50.02) v1(21.55,25.92) v1(21.73,47.81) v1(21.77,39.65) v1(21.82,23.21) v1(21.8,22.59) v1(21.79,14.14) v1(21.79,12.19) v1(21.88,46.77) v1(21.95,23.96) v1(22.11,48.63) v1(22.07,19.61) v1(22.17,42.18) v1(22.17,41.5) v1(22.24,40.42) v1(22.28,47.41) v1(22.27,36.42) v1(22.44,36.99) v1(22.41,14.14) v1(22.51,29.35) v1(22.52,28.62) v1(22.52,27.9) v1(22.57,50.09) v1(22.74,40.96) v1(22.69,20.11) v1(22.7,18.85) v1(22.84,42.16) v1(22.84,41.52) v1(22.77,35.94) v1(22.93,31.19) v1(22.92,12.2) v1(22.96,48.66) v1(22.98,47.76) v1(23.02,37.51) v1(23.01,36.72) v1(23.13,35.37) v1(23.06,34.8) v1(23.14,20.68) v1(23.2,33.2) v1(23.18,32.51) v1(23.22,29.35) v1(23.18,28.66) v1(23.17,14.12) v1(23.41,19.59) v1(23.52,26.97) v1(23.56,50.1) v1(23.63,48.64) v1(23.65,47.74) v1(23.72,42.18) v1(23.66,41.57) v1(23.92,20.7) v1(23.95,27.46) v1(23.98,26.95) v1(24.05,14.08) v1(24.13,12.2) v1(24.21,20.1) v1(24.38,48.67) v1(24.4,47.77) v1(24.39,42.16) v1(24.4,41.56) v1(24.39,27.41) v1(24.53,32.08) v1(24.52,31.54) v1(24.54,30.75) v1(24.46,28.03) v1(24.45,21.24) v1(24.57,50.11) v1(24.82,40.1) v1(24.85,37.82) v1(24.91,28.04) v1(24.94,20.68) v1(24.87,14.08) v1(25.01,21.97) v1(25.05,48.65) v1(25.07,47.75) v1(25.23,42.16) v1(25.22,41.55) v1(25.37,25.88) v1(25.43,21.21) v1(25.4,20.06) v1(25.43,12.19) v1(25.58,50.1) v1(25.67,40.16) v1(25.67,21.92) v1(25.65,14.14) v1(25.8,48.65) v1(25.82,47.75) v1(25.84,26.36) v1(25.9,42.14) v1(25.94,41.54) v1(25.87,36.37) v1(26.01,35.82) v1(25.96,20.68) v1(26.27,14.14) v1(26.35,26.88) v1(26.38,22.01) v1(26.43,20.11) v1(26.47,48.63) v1(26.49,47.73) v1(26.52,40.16) v1(26.54,32.65) v1(26.52,31.78) v1(26.53,21.2) v1(26.63,35.71) v1(26.56,30.84) v1(26.58,30.25) v1(26.56,12.2) v1(26.69,50.09) v1(26.72,42.11) v1(26.74,41.53) v1(26.97,29.8) v1(26.98,29.11) v1(27.02,28.27) v1(27.03,27.46) v1(27.03,20.67) v1(27.03,14.12) v1(27.09,30.51) v1(27.22,40.17) v1(27.16,21.92) v1(27.3,48.6) v1(27.32,47.7) v1(27.39,42.09) v1(27.6,41.55) v1(27.55,30.88) v1(27.58,30.29) v1(27.55,21.18) v1(27.62,20.11) v1(27.68,50.1) v1(27.77,12.2) v1(27.97,48.58) v1(27.99,47.68) v1(27.99,14.04) v1(28.21,42.12) v1(28.18,20.7) v1(28.42,41.55) v1(28.42,39.41) v1(28.48,34.82) v1(28.48,34.23) v1(28.5,33.66) v1(28.49,33.06) v1(28.5,32.45) v1(28.5,31.85) v1(28.69,50.11) v1(28.73,48.58) v1(28.66,20.1) v1(28.75,47.68) v1(28.81,14.04) v1(28.88,42.1) v1(29.05,34.81) v1(29.05,34.22) v1(29.07,33.65) v1(29.06,33.05) v1(29.07,32.44) v1(29.07,31.84) v1(29.16,41.55) v1(29.16,21.89) v1(29.17,12.17) v1(29.34,39.57) v1(29.34,39.2) v1(29.62,48.68) v1(29.58,47.69) v1(29.63,42.13) v1(29.63,34.81) v1(29.63,34.22) v1(29.64,33.05) v1(29.59,14.1) v1(29.7,50.1) v1(29.65,33.65) v1(29.65,32.44) v1(29.65,31.84) v1(29.7,20.09) v1(29.76,24.77) v1(29.87,41.57) v1(30.23,34.81) v1(30.23,34.22) v1(30.24,33.05) v1(30.15,25.18) v1(30.16,18.53) v1(30.21,14.1) v1(30.29,48.66) v1(30.25,47.67) v1(30.3,42.11) v1(30.25,33.65) v1(30.25,32.44) v1(30.25,31.84) v1(30.3,12.18) v1(30.56,41.55) v1(30.55,25.59) v1(30.57,21.9) v1(30.67,20.09) v1(30.92,50.1) v1(30.87,34.82) v1(30.87,34.23) v1(30.89,33.66) v1(30.88,33.06) v1(30.89,32.45) v1(30.89,31.85) v1(30.92,19.37) v1(31.04,48.69) v1(31,47.7) v1(30.96,26.05) v1(30.97,14.08) v1(31.05,42.11) v1(31.18,29.82) v1(31.17,29.07) v1(31.18,28.47) v1(31.2,27.79) v1(31.2,27.21) v1(31.21,26.58) v1(31.15,21.92) v1(31.26,41.59) v1(31.48,34.81) v1(31.48,34.22) v1(31.5,33.65) v1(31.49,33.05) v1(31.5,32.44) v1(31.5,31.84) v1(31.51,12.18) v1(31.71,48.67) v1(31.67,47.68) v1(31.72,42.09) v1(31.73,27.07) v1(31.73,20.08) v1(31.91,50.11) v1(31.91,41.39) v1(31.96,14.11) v1(32.07,20.99) v1(32.42,47.68) v1(32.46,48.67) v1(32.55,42.06) v1(32.55,41.38) v1(32.61,12.17) v1(32.78,14.11) v1(32.92,50.12) v1(32.85,38.83) v1(32.86,38.39) v1(32.87,37.93) v1(33.13,48.65) v1(33.09,47.66) v1(33.22,42.04) v1(33.22,41.4) v1(33.48,37.93) v1(33.56,14.17) v1(33.7,46.59) v1(33.74,12.18) v1(33.93,50.11) v1(33.92,47.63) v1(33.94,22.03) v1(33.96,48.62) v1(33.98,42.04) v1(33.99,41.21) v1(34.13,38.86) v1(34.13,38.41) v1(34.14,37.97) v1(34.07,24.34) v1(34.18,14.17) v1(34.29,36.21) v1(34.28,35.73) v1(34.34,23.12) v1(34.44,29.14) v1(34.45,46.58) v1(34.63,48.6) v1(34.59,47.61) v1(34.55,22.29) v1(34.79,50.02) v1(34.94,41.16) v1(34.87,23.65) v1(34.94,14.15) v1(35,49.29) v1(34.99,38.87) v1(34.95,12.18) v1(35.21,46.54) v1(35.28,48.29) v1(35.35,47.61) v1(35.41,38.27) v1(35.4,36.5) v1(35.42,35.91) v1(35.43,24.72) v1(35.62,22.26) v1(35.79,41.14) v1(35.82,40.4) v1(35.87,23.64) v1(35.93,12.21) v1(36.01,46.57) v1(35.96,25.67) v1(36.03,21.45) v1(36.09,47.23) v1(36.42,42.01) v1(36.49,41.17) v1(36.48,40.7) v1(36.45,35.83) v1(36.49,24.71) v1(36.55,32.06) v1(36.58,31.45) v1(36.58,28.83) v1(36.63,22.26) v1(36.94,46.51) v1(37.04,23.57) v1(37.06,25.65) v1(37.24,41.16) v1(37.16,12.21) v1(37.26,40.7) v1(37.25,31.44) v1(37.6,46.46) v1(37.63,24.72) v1(37.68,22.26) v1(37.84,32.26) v1(37.87,31.45) v1(38.04,41.19) v1(38.05,40.69) v1(38.11,25.7) v1(38.29,34.35) v1(38.25,23.53) v1(38.49,32.26) v1(38.5,31.46) v1(38.52,12.26) v1(38.63,41.56) v1(39.01,41.09) v1(38.99,32.46) v1(39.01,31.73) v1(39.01,30.99) v1(39.46,40.67) v1(39.5,28.61) v1(39.48,27.91) v1(39.57,39.89) v1(39.61,39.23) v1(39.61,34.42) v1(39.65,32.71) v1(39.65,32.1) v1(39.66,31.47) v1(39.68,30.79) v1(39.69,29.69) v1(39.75,35.18) v1(39.9,46.46) v1(39.88,40.42) v1(39.98,11.62) v1(40.05,28.55) v1(40.24,31.07) v1(40.27,38.09) v1(40.31,35.18) v1(40.32,34.43) v1(40.27,30.38) v1(40.25,29.76) v1(40.27,29.19) v1(40.36,32.71) v1(40.4,31.94) v1(40.68,46.92) v1(41,35.23) v1(41.04,34.45) v1(40.97,29.34) v1(40.98,10.47) v1(41.16,39.18) v1(41.32,32.69) v1(41.32,31.9) v1(41.32,31.08) v1(41.28,30.23) v1(41.42,47.61) v1(41.4,9.19) v1(41.68,8.04) v1(41.82,20.99) v1(41.94,6.97) v1(41.97,48.51) v1(42.25,5.91) v1(42.36,49.34) v1(42.51,4.89) v1(42.56,21.28) v1(42.59,20.54) v1(43.25,3.97) v1(43.44,19.92) v1(44.12,23.53) v1(44.19,19.4) v1(44.37,45.31) v1(44.6,3.89) v1(44.85,23.45) v1(44.98,25.73) v1(45.22,39.49) v1(45.23,38.41) v1(45.23,37.34) v1(45.23,34.13) v1(45.24,30.36) v1(45.3,45.08) v1(45.25,36.17) v1(45.25,35.14) v1(45.25,31.09) v1(45.27,29.55) v1(45.29,28.8) v1(45.35,28) v1(45.54,25.73) v1(45.52,19.33) v1(45.64,23.49) v1(45.89,27.32) v1(45.85,26.4) v1(45.85,3.9) v1(46.03,49.22) v1(46.04,28.5) v1(46.19,46.31) v1(46.19,25.73) v1(46.22,22.9) v1(46.3,25.05) v1(46.33,24.27) v1(46.35,23.53) v1(46.37,22.31) v1(46.59,45.22) v1(46.56,27.9) v1(46.84,22.92) v1(46.85,27.01) v1(46.85,26.38) v1(46.85,25.76) v1(46.92,25.06) v1(46.94,24.3) v1(46.95,23.56) v1(46.98,19.33) v1(47.17,3.88) v1(48.04,32.19) v1(48.03,30.84) v1(48.2,35.52) v1(48.15,19.99) v1(48.32,3.9) v1(48.42,43.63) v1(48.54,41.34) v1(48.61,42.93) v1(48.58,42.16) v1(48.61,40.54) v1(48.71,39.74) v1(48.67,38.92) v1(48.69,38.06) v1(48.76,35.52) v1(48.85,29.75) v1(49.05,20.93) v1(49.32,37.97) v1(49.45,3.9) v1(49.56,28.99) v1(49.63,27.77) v1(49.65,43.46) v1(49.67,26.48) v1(49.69,23.45) v1(49.79,22.16) v1(49.92,38.02) v1(50.59,38.08) v1(50.71,3.9) v1(50.84,43.42) v1(50.93,37.41) v1(50.98,36.46) v1(51,35.54) v1(51.36,42.58) v1(51.47,41.53) v1(51.6,40.47) v1(51.73,39.26) v1(51.79,38) v1(51.93,36.73) v1(52.01,35.54) v1(52.17,33.81) v1(52.28,32.58) v1(52.41,31.22) v1(52.54,30.08) v1(52.63,28.89) v1(52.62,27.45) v1(52.73,26.22) v1(52.86,24.86) v1(52.99,23.72) v1(53.08,22.53) v1(53.18,21.27) v1(53.29,20.04) v1(53.42,18.68) v1(53.55,17.54) v1(53.64,16.35) v1(53.67,14.93) v1(53.72,3.92) v1(53.78,13.7) v1(53.91,12.34) v1(54.13,10.01) v1(54.38,8.62) v1(54.55,7.19) v1(54.7,5.82) v1(54.68,4.52)
VDD_1V8: length 65.5
  TOP w0.254: 40.37,36.22 R19.1 ; C36.1 40.53,38.92 41.03,38.41 41.03,36.87 40.5,36.33 ; R7321.1 24.04,28.93 R7322.1 22.97,30.09 22.45,30.61 22.45,34.88 21.33,36 20.18,36 R7306.1 ; v1(34.41,25.63) 34.43,25.62 R7323.1 34.85,25.54 v1(34.85,25.63)
  TOP w0.5: v1(32.57,40.59) 31.54,40.59 ; 31.54,40.59 31.91,40.22 31.91,39.47 R7308.2 ; 31.54,40.59 31.33,40.8 23.9,40.8 22.83,39.73 22.83,39.32 ; Y1.4 37.53,37.67 L5.2 40.37,36.22 ; v1(34.41,25.63) v1(34.85,25.63) 34.85,26.55 L6.2 33.63,26.56 R7.1 ; 22.83,39.32 20.05,36.54 R7306.1 ; 22.83,39.32 L4.2 25.37,39.32 R3.1 R2.1 R5.1 ; R19.1 40.5,36.33 v1(40.8,36.33) v1(41.17,36.33)
  POWER w0.5: 38.72,36.33 v1(40.8,36.33) ; 38.72,36.33 35.78,33.39 35.78,26.56 v1(34.85,25.63) ; 38.72,36.33 34.46,40.59 v1(33.05,40.59) v1(32.57,40.59)
VDD_5V: length 59.2
  TOP w0.127: C7346.2 v1(8.33,34.02) ; 32.32,44.92 R7286.2 ; 9.29,25.97 9.52,25.97
  TOP w0.254: R7311.2 9.77,17.25 v1(9.1,17.25)
  TOP w0.4: 12.98,30.8 U2109.2 ; 12.98,30.8 13.28,31.1 13.28,31.72 13.65,32.1 U2109.4 ; 12.98,30.8 U2109.7
  TOP w0.5: R7311.2 9.11,17.24 v1(9.1,17.25) v1(9.1,17.74) ; v1(8.64,26.32) 8.64,26.31 v1(8.93,26.02) 9.47,26.02 R7312.2 ; v1(31.96,46.21) v1(32.45,46.21) ; v1(32.21,45.76) v1(31.74,45.76)
  POWER w0.5: v1(32.45,46.21) 32.45,46 v1(32.21,45.76) ; v1(8.33,34.02) 8,34.02 8,33.66 6.72,32.38 6.72,28.29 7.5,27.51 7.5,27.45 v1(8.93,26.02) 9.27,25.68 9.27,24.39 8.58,23.71 8.58,18.26 v1(9.1,17.74) ; v1(31.51,46.21) v1(31.96,46.21)
  POWER w1: v1(31.51,46.21) 31.42,46.12 23.07,46.12 16.97,40.02 13.77,40.02 8.33,34.58 v1(8.33,34.02)
  vias: v1(8.09,34.61) v1(8.11,33.52) v1(8.54,34.6) v1(8.58,33.54)
VDD_LDO: length 18.3
  TOP w0.5: R7318.2 20.96,34.94 v1(20.97,34.93) ; v1(10.63,23.04) 10.62,23.03 10.62,22.65 R7316.2
  POWER w0.5: v1(20.97,34.93) 20.96,34.92 20.96,33.83 10.63,23.51 v1(10.63,23.04)
CAM_1V2: length 20.8
  TOP w0.254: C7509.1 24.63,24.98 24.39,24.74 J1.5 24.39,22.2 v1(23.92,21.73) v1(23.64,21.45)
  TOP w0.5: R7317.2 v1(18.75,19.89) ; v1(20.47,28.33) 20.18,28.62 R7305.2
  POWER w0.5: 22.85,21.45 v1(23.64,21.45) ; 22.85,21.45 21.29,19.89 v1(18.75,19.89) ; 22.85,21.45 21.82,21.45 19.82,23.45 19.82,27.68 v1(20.47,28.33)
CAM_1V8: length 16.6
  TOP w0.254: J1.4 23.89,24.21 23.55,24.55
  TOP w0.3: C7508.1 23.55,24.55
  TOP w0.5: R7310.1 20.74,33.77 21.75,32.76 21.75,27.5 21.93,27.32 21.93,26.68 ; C7508.1 23.45,25.43 22.19,26.68 21.93,26.68 ; 21.93,26.68 21.92,26.67 R7304.2
CAM_3V3: length 36.8
  TOP w0.254: C7510.1 32.27,24.64 32.89,24.01 J1.22 32.89,21.85 ; R7303.2 18.16,15.14 v1(18.79,15.14)
  TOP w0.5: 32.89,21.85 32.89,19.9 28.15,15.16 v1(19.17,15.16) R7303.2 ; R7313.2 v1(9.82,23.44) v1(9.82,23.03)
  POWER w0.5: v1(18.79,15.14) 17.11,15.14 9.82,22.43 v1(9.82,23.03)
CAM_CLK: length 23.2
  TOP w0.254: R1.2 30.88,39.99 30.72,40.15 v1(30.6,40.15) ; J1.2 22.89,24.03 C21.2 22.19,24.76 v1(22.19,25.35)
  POWER w0.254: v1(22.19,25.35) 22.19,26.63 23.89,28.33 23.89,35.88 28.16,40.15 v1(30.6,40.15)
CAM_CLKO: length 4.6
  TOP w0.254: R7309.2 R1.1 ; R1.1 R7308.1 ; R1.1 30.73,38.27 U1.19
CAM_PWD: length 20.5
  TOP w0.254: U1.28 26.37,33.57 v1(26.01,33.21) ; v1(26.02,28.92) R7321.2 ; J1.16 v1(29.89,21.77)
  BOTTOM w0.254: 26.01,28.93 26.01,27.58 24.47,26.04 24.47,23.95 25.22,23.2 29.07,23.2 29.89,22.38 v1(29.89,21.77) ; 26.01,28.93 v1(26.02,28.92) ; 26.01,28.93 v1(26.01,33.21)
CAM_RST: length 24.5
  TOP w0.254: J1.20 31.9,23.1 v1(31.9,21.78) ; v1(25.92,33.89) 26.1,34.07 U1.27 ; v1(25.51,30.53) 25.07,30.09 R7322.2
  BOTTOM w0.254: v1(25.92,33.89) 25.51,33.48 v1(25.51,30.53) 25.51,27.63 24.03,26.15 24.03,23.65 24.99,22.69 28.25,22.69 28.66,22.28 28.66,21.45 29.23,20.88 31,20.88 v1(31.9,21.78)
CAM_SCL: length 24.7
  TOP w0.254: U1.24 28.01,36.09 27.15,36.09 v1(26.4,36.84) 25.48,37.76 R3.2 ; v1(31.06,24.32) 30.89,24.15 J1.18
  BOTTOM w0.254: v1(31.06,24.32) 33.02,26.28 33.02,35.26 31.86,36.42 28.36,36.42 27.64,37.14 26.7,37.14 v1(26.4,36.84)
CAM_SDA: length 22.8
  TOP w0.254: U1.23 28.73,36.44 28.51,36.66 v1(27.31,36.66) 27.31,36.71 26.58,37.44 R2.2 ; v1(30.39,24.2) J1.17
  BOTTOM w0.254: v1(30.39,24.2) 30.39,24.64 32.52,26.77 32.52,35.06 31.67,35.91 28.06,35.91 v1(27.31,36.66)
CAM_SYNC: length 17.3
  TOP w0.254: U1.18 31.23,36.76 31.53,37.06 31.53,37.07 31.61,37.15 SYNC.1 v1(32.84,37.15) ; v1(33.39,25.73) 33.39,25.14 R7323.2 33.39,25.09 J1.23
  POWER w0.254: v1(33.39,25.73) 33.76,26.1 33.76,36.29 32.9,37.15 v1(32.84,37.15)
CLK_IN: length 7.6
  TOP w0.254: v1(32.94,39.53) C7502.2 33.57,39.62 R20.2 ; v1(29.98,37.52) 29.98,37.44 30.22,37.2 30.22,35.88 U1.20
  POWER w0.254: v1(29.98,37.52) 31.99,39.53 v1(32.94,39.53)
CSI_CKN: length 8.8
  TOP w0.178: U1.6 30.73,30.32 30.67,30.26 30.67,28.56 29.93,27.83 v1(29.91,27.83) ; J1.13 28.39,23.78 28.52,23.91 28.52,24.34 v1(28.38,24.48)
  BOTTOM w0.178: v1(29.91,27.83) 29.99,27.75 29.99,26.4 28.51,24.91 28.51,24.61 v1(28.38,24.48)
CSI_CKP: length 8.7
  TOP w0.178: v1(29.03,24.68) 28.91,24.56 28.91,23.75 28.89,23.72 J1.14 ; v1(29.96,28.53) 30.02,28.47 30.27,28.73 30.27,30.29 30.23,30.34 U1.5
  BOTTOM w0.178: v1(29.96,28.53) 30.02,28.47 30.05,28.47 30.39,28.13 30.39,26.24 29.03,24.88 v1(29.03,24.68)
CSI_D0N: length 9.1
  TOP w0.178: U1.4 29.73,30.33 29.67,30.26 29.67,29.16 29,28.5 v1(28.8,28.5) ; v1(26.86,24.63) 26.94,24.55 26.94,23.9 26.89,23.85 J1.10
  BOTTOM w0.178: v1(28.8,28.5) 28.86,28.44 28.86,28.32 28.9,28.28 28.9,26.85 26.99,24.94 26.99,24.76 v1(26.86,24.63)
CSI_D0P: length 8.8
  TOP w0.178: U1.3 29.23,30.33 29.27,30.29 29.27,29.39 29,29.12 28.97,29.12 v1(28.96,29.13) ; J1.11 27.39,23.81 27.33,23.87 27.33,24.51 27.49,24.66 v1(27.49,24.73)
  BOTTOM w0.178: v1(28.96,29.13) 28.99,29.1 28.99,29.04 29.28,28.75 29.28,28.46 29.29,28.45 29.29,26.69 27.49,24.89 v1(27.49,24.73)
CSI_D1N: length 9.2
  TOP w0.178: J1.7 25.39,23.83 25.44,23.89 25.44,24.52 v1(25.36,24.61) ; U1.2 28.73,30.36 28.68,30.31 28.68,29.65 27.81,28.79 v1(27.75,28.79)
  BOTTOM w0.178: v1(27.75,28.79) 27.76,28.79 27.8,28.79 27.84,28.75 27.84,27.35 25.38,24.89 25.38,24.62 v1(25.36,24.61)
CSI_D1P: length 9.1
  TOP w0.178: J1.8 25.89,23.78 25.84,23.83 25.84,24.56 v1(25.98,24.7) ; U1.1 28.23,30.37 28.28,30.32 28.28,29.82 27.97,29.5 27.88,29.5 27.87,29.51 v1(27.86,29.51)
  BOTTOM w0.178: v1(25.98,24.7) 25.98,24.94 28.23,27.19 28.23,28.75 28.24,28.76 28.24,29.06 27.87,29.43 27.87,29.5 v1(27.86,29.51)
FDP-LINK+: length 9
  TOP w0.178: R7319.2 43.99,33.73 C10.2
FDP-LINK-: length 5.7
  TOP w0.178: R7307.2 38.44,33.34 43.4,33.34 43.69,33.06 R7320.2
PWR_5V: length 32.1
  TOP w0.254: 48.2,23.18 48.23,23.21 UNK5V.1
  TOP w1.5: J3.7 44.78,21.05 46.91,21.05 48.2,22.34 v1(48.2,26.13)
  BOTTOM w1.5: v1(48.2,26.13) 48.2,28.26 46.7,29.76 46.7,41.14 42.56,45.28 v1(42.08,45.28)
  vias: v1(41.45,45.41) v1(41.73,45.02) v1(41.77,45.83) v1(42.25,45.81) v1(47.78,27.31) v1(47.79,26.65) v1(47.8,25.57) v1(47.81,24.98) v1(48.58,27.3) v1(48.55,26.63) v1(48.58,25.56) v1(48.58,25)
SPK+: length 39.2
  TOP w0.254: R7292.1 v1(25.04,43.22) 26.35,43.22 v1(26.47,43.1) ; J3.4 39.91,24.66 SPK-.1
  BOTTOM w1: v1(26.47,43.1) 38.5,43.1 42.43,39.17 42.43,29.36 39.28,26.22 J3.4
  vias: v1(24.66,43.21) v1(25.44,43.2) v1(25.85,43.19)
SPK-: length 41.1
  TOP w0.254: v1(25.41,44.52) v1(25.03,44.52) v1(24.66,44.52) R7291.1 ; v1(25.41,44.52) 25.42,44.51 ; v1(25.41,44.52) v1(25.81,44.52) 26.5,44.52 v1(26.53,44.55) ; SPK+.1 41.22,24.27 J3.3
  BOTTOM w1: v1(26.53,44.55) 26.54,44.54 39.33,44.54 44.01,39.86 44.01,28.66 41.27,25.93 J3.3
VOL+: length 38.2
  TOP w0.254: R7209.1 13.93,12.03 15.17,13.27 35.1,13.27 VOL+.1 37.58,14.93 39.46,16.81 J3.5
VOL-: length 59.6
  TOP w0.254: 35.96,13.22 35.57,12.83 15.45,12.83 14.09,11.47 9.84,11.47 7.1,8.73 4.54,8.73 2.77,10.5 2.77,17.53 4.83,19.59 R7288.1 ; 35.96,13.22 35.98,13.24 VOL-.1 ; 35.96,13.22 36.73,13.22 40.02,16.51 40.02,20.79 41.45,22.22
N00294: length 5.2
  TOP w0.254: C3.1 25.74,34.57 U1.26
  TOP w0.5: C1.1 25.34,32.47 C2.1 C3.1
N00623: length 5
  TOP w0.254: C4.1 36.03,34.91 C5.1 C6.1 34.9,34.99 34.09,34.99 33.67,34.57 U1.15
N01072: length 6.3
  TOP w0.254: 33.25,30.86 33.25,31.81 32.99,32.07 U1.10
  TOP w0.5: C7.1 37.12,29.95 C8.1 C9.1 34.16,29.95 33.25,30.86
N03572: length 2.6
  TOP w0.178: U1.14 33.71,34.07 34.04,33.74 34.94,33.74 C10.1
N03592: length 2.8
  TOP w0.178: C7352.1 34.81,32.8 34.77,32.84 34.77,32.84 34.52,33.1 34.51,33.1 34.39,33.22 33.9,33.22 33.55,33.57 U1.13
N03606: length 7.1
  TOP w0.178: R7302.1 45.75,33.01 47.2,33.01 J2.1
  TOP w0.254: 49.94,32.89 J2.1
  TOP w0.6: L1.1 J2.1
N03646: length 1.4
  TOP w0.178: C7352.2 36.33,33.15 R7307.1 37.25,33.13
N04688: length 5.5
  TOP w0.254: C12.1 25.12,35.07 U1.25
  TOP w0.5: L4.1 24.08,37.44 25.05,36.48 C13.1 C12.1
N05216: length 6.5
  TOP w0.254: 32.53,35.47 U1.16
  TOP w0.5: L5.1 36.31,37.29 C15.1 34.94,37.29 C14.1 34.37,37.32 32.53,35.47
N05348: length 14.1
  TOP w0.254: 34.5,30.68 34.12,31.06 34.12,31.49 33.04,32.57 U1.11
  TOP w0.5: C18.1 35.95,27.05 L6.1 36.52,26.63 37.91,26.63 38.66,27.39 C17.1 C16.1 38.19,30.68 34.5,30.68
N05546: length 3.4
  TOP w0.254: C18.2 34.81,27.71
  TOP w0.5: 34.81,27.71 32.53,29.99
N05630: length 3.1
  TOP w0.254: U1.12 33.16,33.08 34.78,31.45 C19.1
N08569: length 4
  TOP w0.254: U1.21 29.73,36.76 28.8,37.69 28.8,38.4 R6.2 R5.2
N08620: length 4.3
  TOP w0.254: 31.73,28.57 U1.8
  TOP w0.3: C20.1 31.73,28.57
  TOP w0.5: C20.1 33.19,28.02 R7.2
N20067: length 1.9
  TOP w0.254: Y1.1 39.57,37.23 R19.2
N20534: length 1.6
  TOP w0.254: Y1.3 37.48,39.62 R20.1
N40133: length 5.9
  TOP w0.5: U2105.3 12.62,14.86 R7281.1 C6893.2 11.08,16.13 11.08,16.5 ; R7311.1 11.08,16.5 ; 11.08,16.5 11.29,16.71 U2105.1
N40219: length 1.8
  TOP w0.5: C6895.2 16.34,14.06 U2105.4
N40223: length 4.1
  TOP w0.5: R7303.1 C6894.2 C6999.1 16.37,16.71 U2105.5
N40778: length 7.6
  TOP w0.5: U2106.1 12.41,26.91 C7011.2 11.12,26.77 R7312.1 R7313.1 12.34,24.36 12.55,24.58 ; U2106.3 12.55,24.58 ; 12.55,24.58 R7282.1
N40864: length 1.7
  TOP w0.5: U2106.4 15.97,24.38 C7013.2
N40868: length 4.1
  TOP w0.5: C7014.1 C7012.2 17.17,26.66 R7304.1 17.1,26.62 U2106.5
N92182: length 5.3
  TOP w0.254: R7209.2 7.71,12.04 T31.1 VOL+1.1 5.48,11.62 J2527.1
N92991: length 5.2
  TOP w0.254: J2528.1 5.16,23.81 4.84,23.48 4.84,22.75 T32.1 ; VOL-1.1 T32.1 ; T32.1 R7288.2
N121471: length 3
  TOP w0.254: U2109.1 14.13,29.08 R2568.2 R2567.1
N129833: length 2.8
  TOP w0.254: 11.03,28.67 10.98,28.72 R7297.1 ; 11.03,28.67 U2109.8 ; 11.03,28.67 R7298.2
N129837: length 17.4
  TOP w0.5: 13.48,35.56 v1(13.48,35.07) ; 13.48,35.56 14.06,34.98 14.54,34.98 14.96,34.56 14.96,34.44 C7350.2 C7351.2 18.91,33.92 ; 13.48,35.56 L1004.2 ; 18.91,33.92 R7310.2 ; 18.91,33.92 18.91,33.93 R7318.1 19.03,35.07 R7306.2 ; R7297.2 9.77,29.74 9.77,30.15 9.55,30.37 v1(9.55,30.4)
  POWER w0.5: v1(13.48,35.07) 11.88,35.07 9.83,33.02 9.83,31.39 9.55,31.11 v1(9.55,30.4)
N133411: length 13.2
  TOP w0.5: T34.1 13.4,38.45 J2529.1
  TOP w0.6: R7292.2 22.18,43.42 C7322.2 C7501.1 19.18,43.42 SPK+1.1 18.88,41.54 17.49,40.15 13.52,40.15 J2529.1
N133415: length 16.8
  TOP w0.127: 18.07,43.65 18.82,44.39 arc(18.85,44.44) SPK-1.1
  TOP w0.5: J2529.2 12.15,38.5 T33.1
  TOP w0.6: J2529.2 12.15,41.03 12.76,41.63 13.85,41.63 14.31,41.17 16.99,41.17 17.9,42.07 17.9,43.47 18.86,44.44 19,44.3 19.8,44.3 C7501.2 19.98,44.32 C7321.2 22.18,44.32 R7291.2
N134026: length 8.5
  TOP w0.178: R7319.1 44.4,31.67 44.4,27.04 44.65,26.78 F_LK+.1 44.41,26.28 44.41,25.41 J3.1
N134032: length 8.4
  TOP w0.178: R7320.1 43.69,31.85 44,31.54 44,27.02 F_LK-.1 44.02,26.24 44.02,25.14 43.27,24.39
N180611: length 5.9
  TOP w0.5: U2110.1 12.53,21.93 R7316.1 11.2,20.78 C7503.2 R7314.1 11.51,19.88 U2110.3
N180695: length 3.9
  TOP w0.5: R7317.1 17.12,19.9 C7504.2 C7506.1 16.8,21.78 U2110.5
N180699: length 2.3
  TOP w0.5: U2110.4 15.6,19.43 16.28,18.75 17.11,18.75 C7505.2

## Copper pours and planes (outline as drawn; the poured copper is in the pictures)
GND on TOP: 1.49,0.3 0.61,0.69 0.3,1.61 3.22,33.69 3.63,34.11 3.81,34.67 4.73,44.81 4.96,45.27 5.43,45.45 6.95,45.45 9.18,46.37 10.1,48.6 10.1,49.8 10.3,50.29 10.8,50.5 13.51,50.5 14,50.31 14.21,49.83 17.61,46.6 21,49.83 21.22,50.31 21.7,50.5 34.51,50.5 35,50.31 35.21,49.83 38.27,46.62 41.9,49.16 42.15,49.54 42.58,49.69 45.76,49.69 46.25,49.49 46.46,48.99 46.46,46.91 47.38,44.68 49.61,43.76 50.94,43.76 51.41,43.58 51.64,43.12 55.12,4.91 54.81,3.99 53.92,3.6 43.48,3.6 42.75,3.85 42.32,4.49 40.99,9.46 39.82,11.22 37.81,11.9 18.41,11.9 16.4,11.22 15.22,9.46 13.01,1.19 12.58,0.55 11.85,0.3 ; 3 cut-outs
GND on BOTTOM, GND, POWER: 1.49,0.3 0.61,0.69 0.3,1.61 3.22,33.69 3.63,34.11 3.81,34.67 4.73,44.81 4.96,45.27 5.43,45.45 6.95,45.45 9.18,46.37 10.1,48.6 10.1,49.8 10.3,50.29 10.8,50.5 13.51,50.5 14,50.31 14.21,49.83 17.61,46.6 21,49.83 21.22,50.31 21.7,50.5 34.51,50.5 35,50.31 35.21,49.83 38.27,46.62 41.9,49.16 42.15,49.54 42.58,49.69 45.76,49.69 46.25,49.49 46.46,48.99 46.46,46.91 47.38,44.68 49.61,43.76 50.94,43.76 51.41,43.58 51.64,43.12 55.12,4.91 54.81,3.99 53.92,3.6 43.48,3.6 42.75,3.85 42.32,4.49 40.99,9.46 39.82,11.22 37.81,11.9 18.41,11.9 16.4,11.22 15.22,9.46 13.01,1.19 12.58,0.55 11.85,0.3
VDD_1V8 on TOP (solid shape): 34.41,26.92 35.3,26.92 35.3,25.66 35.05,25.41 35.05,25.4 34.28,25.4 33.23,26.45 33.23,27.03 34.3,27.03
VDD_5V on TOP (solid shape): 32.83,46.23 32.83,44.62 32.75,44.54 31.94,44.54 31.28,45.2 31.28,46.33 31.44,46.49 32.57,46.49
VDD_5V on TOP (solid shape): 12.02,33.61 11.24,33.61 10.46,32.83 10.46,31.14 10.63,30.97 11.35,30.97 11.35,30.62 9.99,30.62 9.7,30.91 9.7,31.86 7.86,33.69 7.86,35 12.02,35
VDD_5V on POWER (solid shape): 8.84,33.26 7.84,33.26 7.84,35 8.84,35
VDD_5V on POWER (solid shape): 32.69,45.51 31.23,45.51 31.23,46.7 32.69,46.7
POC_V on TOP (solid shape): 39.87,45.82 39.87,44.84 40.17,44.54 46.78,44.54 47.92,43.4 47.92,42.63 47.91,42.62 47.33,42.62 46.94,43.01 43.49,43.01 43.28,43.22 39.33,43.22 38.84,43.71 34.04,43.71 33.15,44.6 33.15,45.68 33.4,45.93 39.76,45.93
PWR_5V on TOP (solid shape): 42.55,44.79 40.4,44.79 40.4,46.09 42.55,46.09
PWR_5V on TOP (solid shape): 48.94,24.68 47.45,24.68 47.45,27.76 48.94,27.76
PWR_5V on BOTTOM (solid shape): 42.48,44.8 41.23,44.8 41.23,46.03 42.48,46.03
PWR_5V on BOTTOM (solid shape): 48.94,24.68 47.45,24.68 47.45,27.76 48.94,27.76
SPK+ on TOP (solid shape): 26.72,42.82 23.52,42.82 23.52,43.61 26.72,43.61
SPK+ on BOTTOM (solid shape): 26.52,42.61 24.43,42.61 24.43,43.6 26.52,43.6
SPK- on TOP (solid shape): 26.74,44.12 23.52,44.12 23.52,44.91 26.74,44.91
SPK- on BOTTOM (solid shape): 26.74,44.05 24.45,44.05 24.45,45.04 26.74,45.04
N05546 on TOP (solid shape): 32.95,31.57 32.72,31.34 32.72,30.06 32.5,29.84 32.34,29.84 32.28,29.9 32.28,31.33 32.11,31.5 32.11,31.7 32.95,31.7
N10872 on TOP (solid shape): 50.18,36.38 47.27,36.38 47.27,37.22 50.18,37.22
N10876 on TOP (solid shape): 48.06,37.68 47.26,37.68 47.26,39.72 48.06,39.72
N10907 on TOP (solid shape): 47.92,42.21 47.92,40.09 42.95,40.09 42.8,40.24 42.8,41.57 43.46,42.23 47.9,42.23
N121438 on TOP (solid shape): 16.98,31.52 16.68,31.22 13.88,31.22 13.78,31.32 13.78,31.62 14.58,31.62 14.78,31.82 14.78,32.32 14.98,32.52 16.98,32.52
N121478 on TOP (solid shape): 20.54,30.63 20.54,29.76 20.37,29.59 19.03,29.59 18.62,29.18 18.62,28.36 18.61,28.35 16.55,28.35 16.55,29.1 16.1,29.55 14.97,29.55 14.97,30.47 17.1,30.47 17.3,30.67 20.5,30.67
N131151 on TOP (solid shape): 14.48,33.42 14.38,33.42 12.18,31.22 10.68,31.22 10.68,31.62 11.48,31.62 12.48,32.62 12.48,34.27 14.48,34.27

Small or netless copper shapes (teardrops, artwork), in the pictures only: 20 on TOP, 6 on POWER

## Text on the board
Ref Des/Silkscreen Top: SPK1+ | SPK1- | FPD-Link_Serializer_Ver1.0 | 1 | sync | VOL+ | VOL- | 24 | +5V | GND | spk+ | spk- | Flink- | Flink+
